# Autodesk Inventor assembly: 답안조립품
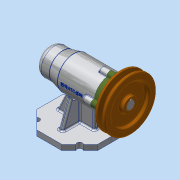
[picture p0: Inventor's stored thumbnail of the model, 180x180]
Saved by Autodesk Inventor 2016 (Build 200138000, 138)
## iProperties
Created: 2019-12
Part Number: 답안조립품
Document SubType Name: Weldment
Designer: 2-PC10
Weld Material: Welded Aluminum-6061
Author: 2-PC10
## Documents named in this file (12)
- C:\Users\2-PC10\Desktop\491204V1059\답안조립품.iam
- C:\Users\2-PC10\Desktop\491204V1059\본체.ipt
- C:\Users\2-PC10\Desktop\491204V1059\베어링 6004.ipt
- C:\Users\2-PC10\Desktop\491204V1059\어댑터슬리브.ipt
- C:\Users\2-PC10\Desktop\491204V1059\볼트 M4.ipt
- C:\Users\2-PC10\Desktop\491204V1059\베어링 51202.ipt
- C:\Users\2-PC10\Desktop\491204V1059\축.ipt
- C:\Users\2-PC10\Desktop\491204V1059\커버.ipt
- C:\Users\2-PC10\Desktop\491204V1059\오일 실.ipt
- C:\Users\2-PC10\Desktop\491204V1059\V벨트풀리.ipt
- C:\Users\2-PC10\Desktop\491204V1059\멈춤나사 M3.ipt
- C:\Users\2-PC10\Desktop\491204V1059\키 5 x 5 x 16.ipt
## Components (1 placed, 1 different names)
1. V벨트풀리:1
